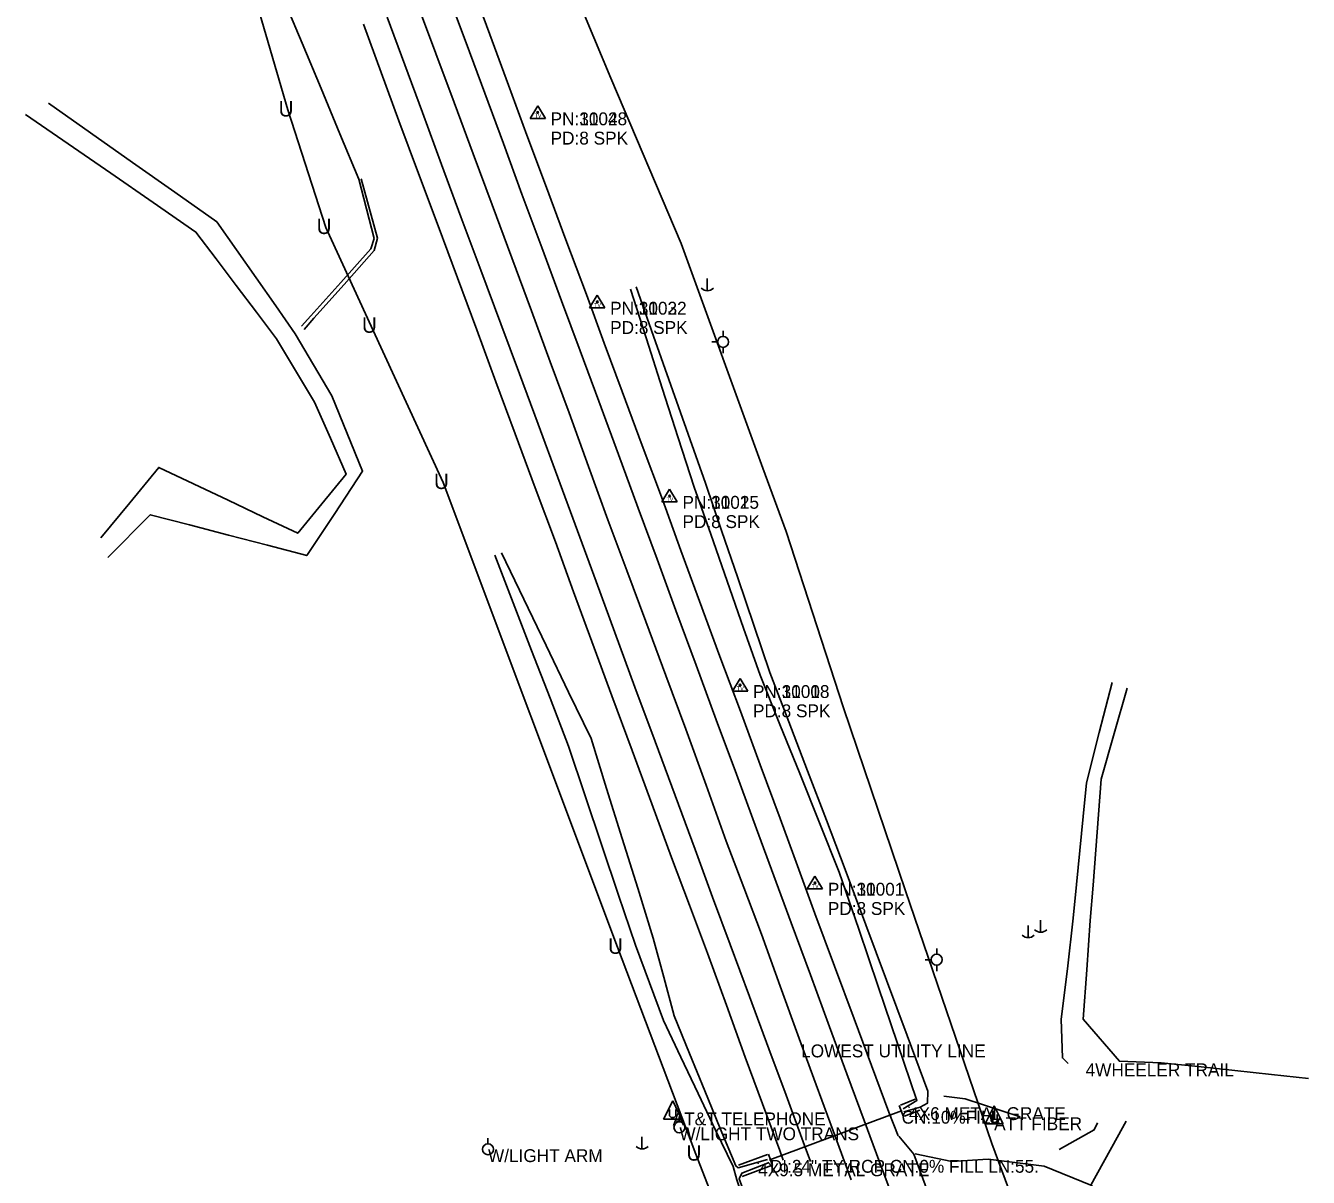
# Model space of a CAD drawing. Extents: x 954793 to 988390, y 1867850 to 1924428.
# Drawn here: x 987603.9 to 988102.4, y 1868765.9 to 1869213.7 of the extents above; entities that cross this region are included whole.
import ezdxf

# ---------------------------------------------------------------- set-up
doc = ezdxf.new("R2010")
doc.units = 0
for name, color, linetype in [('Default', 7, 'Continuous'), ('S_CROSS_DRAIN', 7, 'Continuous'), ('S_CROSS_DRAIN_ANNOT', 7, 'Continuous'), ('S_DITCHLINE', 7, 'Continuous'), ('S_DRG_PT_SYM', 7, 'Continuous'), ('S_DRIVEWAY', 7, 'Continuous'), ('S_EDGE_PAVEMENT', 7, 'Continuous'), ('S_ELECTRIC_UTILITIES_ANNOT', 7, 'Continuous'), ('S_FIBER_OPTIC_CABLE', 7, 'Continuous'), ('S_GRD_PT_SYM', 7, 'Continuous'), ('S_MSC_PT_SYM', 7, 'Continuous'), ('S_PAVEMENT_CROWN', 7, 'Continuous'), ('S_SECONDARY_CTL', 7, 'Continuous'), ('S_SECONDARY_CTL_ANNOT', 7, 'Continuous'), ('S_SHOULDER', 7, 'Continuous'), ('S_SURVEY_TEXT_ANNOT', 7, 'Continuous'), ('S_TRAILS', 7, 'Continuous'), ('S_UNDERGROUND_CABLE', 7, 'Continuous'), ('S_UTILITY_POLE', 7, 'Continuous'), ('S_UTILITY_POLE_ANNOT', 7, 'Continuous'), ('S_UTL_PT_SYM', 7, 'Continuous'), ('S_WALL', 7, 'Continuous')]:
    doc.layers.add(name, color=color, linetype=linetype)

msp = doc.modelspace()

# ---------------------------------------------------------------- linework, layer by layer
at = {"layer": 'S_CROSS_DRAIN'}
msp.add_line((987893.14, 1868772.73), (987944.34, 1868791.8), dxfattribs=at)
at = {"layer": 'S_DITCHLINE'}
for points in [[(987711.07, 1869096.8), (987714.66, 1869100.79), (987726.32, 1869113.83), (987737.97, 1869126.87), (987739.33, 1869130.88), (987733.37, 1869153.95), (987726.02, 1869171.59), (987718.67, 1869189.23), (987711.33, 1869206.87), (987703.98, 1869224.51)], [(987635.85, 1869006.89), (987652.28, 1869023.55), (987667.49, 1869019.58), (987682.7, 1869015.62), (987697.92, 1869011.65), (987713.13, 1869007.68), (987723.98, 1869024.06), (987734.84, 1869040.44), (987728.87, 1869055.08), (987722.89, 1869069.73), (987715.78, 1869081.78), (987708.67, 1869093.82), (987701.05, 1869104.72), (987693.42, 1869115.61), (987685.8, 1869126.5), (987678.17, 1869137.4), (987661.81, 1869148.93), (987645.45, 1869160.45), (987629.09, 1869171.98), (987612.73, 1869183.51)], [(987633.03, 1869014.52), (987644.3, 1869028.21), (987655.58, 1869041.9), (987669.09, 1869035.52), (987682.59, 1869029.13), (987696.1, 1869022.75), (987709.61, 1869016.36), (987719.01, 1869027.81), (987728.42, 1869039.27), (987722.3, 1869053.3), (987716.18, 1869067.33), (987708.78, 1869079.62), (987701.39, 1869091.9), (987693.55, 1869102.28), (987685.71, 1869112.67), (987677.86, 1869123.05), (987670.02, 1869133.44), (987653.48, 1869144.85), (987636.94, 1869156.27), (987620.4, 1869167.68), (987603.86, 1869179.1)], [(987712.1, 1869095.56), (987715.9, 1869099.89), (987727.62, 1869113.08), (987739.35, 1869126.26), (987740.57, 1869131.03), (987734.29, 1869154.07)], [(987944.91, 1868792.52), (987950.32, 1868795.76), (987942.78, 1868817.97), (987935.23, 1868840.18), (987927.68, 1868862.39), (987920.13, 1868884.61), (987912.43, 1868903.74), (987904.72, 1868922.88), (987897.02, 1868942.02), (987889.32, 1868961.16), (987882.93, 1868979.43), (987876.53, 1868997.69), (987870.14, 1869015.95), (987863.75, 1869034.22), (987857.54, 1869053.46), (987851.33, 1869072.71), (987845.12, 1869091.96), (987838.91, 1869111.21)], [(987945.24, 1868791.46), (987951.57, 1868793.19), (987954.39, 1868794.73), (987954.59, 1868799.5), (987946.55, 1868821.03), (987938.51, 1868842.56), (987930.47, 1868864.09), (987922.43, 1868885.61), (987915.11, 1868904.77), (987907.79, 1868923.92), (987900.47, 1868943.07), (987893.15, 1868962.22), (987886.9, 1868980.61), (987880.64, 1868999), (987874.39, 1869017.39), (987868.14, 1869035.78), (987861.39, 1869054.85), (987854.64, 1869073.92), (987847.89, 1869093), (987841.14, 1869112.07)], [(987903.49, 1868695.28), (987897.13, 1868714.75), (987890.76, 1868734.22), (987885.5, 1868749.56), (987880.23, 1868764.91), (987878.83, 1868770.15), (987872.06, 1868784.34), (987865.3, 1868798.52), (987858.54, 1868812.7), (987851.78, 1868826.88), (987846.31, 1868841.55), (987840.85, 1868856.22), (987834.35, 1868875.57), (987827.85, 1868894.92), (987821.35, 1868914.27), (987814.85, 1868933.62), (987807.68, 1868952.16), (987800.51, 1868970.69), (987793.34, 1868989.23), (987786.17, 1869007.76)], [(987892.25, 1868772.86), (987880.75, 1868769.69), (987879.85, 1868770.38), (987873.86, 1868784.96), (987867.87, 1868799.55), (987861.88, 1868814.13), (987855.89, 1868828.71), (987851.86, 1868843.81), (987847.83, 1868858.91), (987841.78, 1868878.31), (987835.74, 1868897.71), (987829.69, 1868917.12), (987823.64, 1868936.52), (987814.92, 1868954.58), (987806.2, 1868972.65), (987797.48, 1868990.71), (987788.76, 1869008.78)], [(987990.37, 1868789.52), (987969.05, 1868796.5), (987960.71, 1868797.45)], [(987905.32, 1868695.02), (987898.91, 1868714.97), (987892.51, 1868734.92), (987886.89, 1868750.13), (987881.26, 1868765.33), (987882.21, 1868767.55), (987892.86, 1868771.75)]]:
    msp.add_lwpolyline(points, dxfattribs=at)
at = {"layer": 'S_DRG_PT_SYM'}
for points in [[(987944.34, 1868791.8), (987944.34, 1868791.85), (987944.34, 1868791.8), (987944.29, 1868791.8), (987944.34, 1868791.8), (987944.34, 1868791.75), (987944.34, 1868791.8), (987944.39, 1868791.8)], [(987893.14, 1868772.73), (987893.14, 1868772.78), (987893.14, 1868772.73), (987893.09, 1868772.73), (987893.14, 1868772.73), (987893.14, 1868772.68), (987893.14, 1868772.73), (987893.19, 1868772.73)]]:
    msp.add_lwpolyline(points, dxfattribs=at)
at = {"layer": 'S_DRIVEWAY'}
for points in [[(987962.03, 1868730.96), (987960.37, 1868744.14), (987954.75, 1868759.55), (987949.14, 1868774.97), (987943.2, 1868781.9)], [(988084.35, 1868715.79), (988062.66, 1868718.35), (988051.03, 1868738.3), (988034.45, 1868750.58), (988017.86, 1868762.86), (987999.71, 1868770.22), (987977.93, 1868773.05), (987963.85, 1868772.04), (987949.58, 1868775.12)]]:
    msp.add_lwpolyline(points, dxfattribs=at)
at = {"layer": 'S_EDGE_PAVEMENT'}
for points in [[(987943.85, 1868750.23), (987936.81, 1868769.13), (987929.77, 1868788.04), (987923.06, 1868806.23), (987916.35, 1868824.43), (987908.88, 1868844.68), (987901.41, 1868864.93), (987894.67, 1868883.2), (987887.94, 1868901.46), (987880.12, 1868922.64), (987872.31, 1868943.83), (987864.46, 1868965.06), (987856.61, 1868986.3), (987849.29, 1869006.21), (987841.96, 1869026.13), (987834.3, 1869046.93), (987826.63, 1869067.74), (987819.39, 1869087.2), (987812.16, 1869106.66), (987804.46, 1869127.42), (987796.75, 1869148.18), (987789.55, 1869167.8), (987782.35, 1869187.43), (987775.07, 1869206.93), (987767.8, 1869226.43)], [(987908.95, 1868772.07), (987906.1, 1868779.8), (987899.43, 1868797.85), (987892.75, 1868815.9), (987885.21, 1868836.18), (987877.67, 1868856.47), (987870.89, 1868874.92), (987864.1, 1868893.37), (987856.31, 1868914.36), (987848.52, 1868935.34), (987840.71, 1868956.52), (987832.9, 1868977.7), (987825.63, 1868997.52), (987818.36, 1869017.33), (987810.71, 1869038.02), (987803.07, 1869058.71), (987795.81, 1869078.24), (987788.55, 1869097.77), (987780.79, 1869118.57), (987773.03, 1869139.36), (987765.56, 1869159.64), (987758.09, 1869179.93), (987751.22, 1869198.45), (987744.34, 1869216.97)]]:
    msp.add_lwpolyline(points, dxfattribs=at)
at = {"layer": 'S_FIBER_OPTIC_CABLE'}
for p, q in [((987831.33, 1869193.21), (987795.61, 1869278.55)), ((987858.7, 1869128.99), (987831.33, 1869193.21)), ((987890.46, 1869041.59), (987858.7, 1869128.99)), ((987899.49, 1869016.95), (987890.46, 1869041.59)), ((987921.71, 1868948.43), (987899.49, 1869016.95)), ((987945.83, 1868877.35), (987921.71, 1868948.43)), ((987979.41, 1868779.14), (987945.83, 1868877.35)), ((988003.79, 1868713.46), (987979.41, 1868779.14))]:
    msp.add_line(p, q, dxfattribs=at)
at = {"layer": 'S_GRD_PT_SYM'}
msp.add_lwpolyline([(987905.29, 1868817.58), (987905.29, 1868817.63), (987905.29, 1868817.58), (987905.24, 1868817.58), (987905.29, 1868817.58), (987905.29, 1868817.53), (987905.29, 1868817.58), (987905.34, 1868817.58)], dxfattribs=at)
at = {"layer": 'S_MSC_PT_SYM'}
for points in [[(987947.25, 1868793.2), (987947.25, 1868793.25), (987947.25, 1868793.2), (987947.2, 1868793.2), (987947.25, 1868793.2), (987947.25, 1868793.15), (987947.25, 1868793.2), (987947.3, 1868793.2)], [(987888.6, 1868771.37), (987888.6, 1868771.42), (987888.6, 1868771.37), (987888.55, 1868771.37), (987888.6, 1868771.37), (987888.6, 1868771.32), (987888.6, 1868771.37), (987888.65, 1868771.37)]]:
    msp.add_lwpolyline(points, dxfattribs=at)
at = {"layer": 'S_PAVEMENT_CROWN'}
msp.add_lwpolyline([(987924.74, 1868765), (987917.72, 1868784.02), (987911.13, 1868801.96), (987904.54, 1868819.91), (987897.19, 1868840.21), (987889.84, 1868860.51), (987882.99, 1868878.55), (987876.15, 1868896.59), (987868.33, 1868918.35), (987860.5, 1868940.11), (987852.71, 1868961.06), (987844.92, 1868982), (987837.53, 1869001.8), (987830.14, 1869021.59), (987822.62, 1869042.33), (987815.1, 1869063.08), (987807.79, 1869082.94), (987800.47, 1869102.81), (987792.81, 1869123.38), (987785.15, 1869143.94), (987777.79, 1869163.85), (987770.43, 1869183.76), (987763.29, 1869202.83), (987756.15, 1869221.91)], dxfattribs=at)
at = {"layer": 'S_SECONDARY_CTL'}
for p, q in [((987802.91, 1869182.55), (987799.9, 1869177.6)), ((987802.91, 1869182.55), (987805.86, 1869177.6)), ((987799.9, 1869177.6), (987805.86, 1869177.6)), ((987826.05, 1869108.92), (987823.04, 1869103.96)), ((987826.05, 1869108.92), (987828.99, 1869103.96)), ((987823.04, 1869103.96), (987828.99, 1869103.96)), ((987854.16, 1869033.46), (987851.15, 1869028.5)), ((987854.16, 1869033.46), (987857.1, 1869028.5)), ((987851.15, 1869028.5), (987857.1, 1869028.5)), ((987881.57, 1868959.9), (987878.56, 1868954.94)), ((987881.57, 1868959.9), (987884.52, 1868954.94)), ((987878.56, 1868954.94), (987884.52, 1868954.94)), ((987910.67, 1868883.05), (987907.66, 1868878.1)), ((987910.67, 1868883.05), (987913.62, 1868878.1)), ((987907.66, 1868878.1), (987913.62, 1868878.1))]:
    msp.add_line(p, q, dxfattribs=at)
for centre, radius in [((987802.91, 1869179.94), 0.311), ((987802.91, 1869179.94), 0.183), ((987802.91, 1869179.94), 0.103), ((987826.05, 1869106.31), 0.311), ((987826.05, 1869106.31), 0.183), ((987826.05, 1869106.31), 0.103), ((987854.16, 1869030.85), 0.311), ((987854.16, 1869030.85), 0.183), ((987854.16, 1869030.85), 0.103), ((987881.57, 1868957.29), 0.311), ((987881.57, 1868957.29), 0.183), ((987881.57, 1868957.29), 0.103), ((987910.67, 1868880.44), 0.311), ((987910.67, 1868880.44), 0.183), ((987910.67, 1868880.44), 0.103)]:
    msp.add_circle(centre, radius, dxfattribs=at)
at = {"layer": 'S_SHOULDER'}
for points in [[(987943.04, 1868782.07), (987939.32, 1868791.21), (987932.63, 1868809.38), (987925.94, 1868827.55), (987918.3, 1868848.04), (987910.67, 1868868.54), (987903.9, 1868887), (987897.12, 1868905.46), (987889.39, 1868926.28), (987881.66, 1868947.1), (987873.73, 1868968.48), (987865.79, 1868989.87), (987858.59, 1869009.66), (987851.39, 1869029.46), (987843.54, 1869050.44), (987835.69, 1869071.42), (987828.76, 1869090.26), (987821.83, 1869109.11), (987813.87, 1869130.43), (987805.91, 1869151.75), (987798.7, 1869171.11), (987791.5, 1869190.47), (987784.24, 1869210.19), (987776.97, 1869229.91)], [(987898.36, 1868772.64), (987896.98, 1868776.33), (987890.29, 1868794.52), (987883.59, 1868812.7), (987876.26, 1868832.88), (987868.92, 1868853.06), (987861.91, 1868871.7), (987854.91, 1868890.34), (987847.29, 1868911.12), (987839.66, 1868931.89), (987831.77, 1868953.08), (987823.87, 1868974.27), (987816.81, 1868993.61), (987809.75, 1869012.94), (987801.91, 1869033.96), (987794.07, 1869054.98), (987786.67, 1869075.21), (987779.28, 1869095.44), (987771.76, 1869115.64), (987764.24, 1869135.83), (987756.6, 1869156.24), (987748.95, 1869176.64), (987742.06, 1869195.42), (987735.17, 1869214.2)]]:
    msp.add_lwpolyline(points, dxfattribs=at)
at = {"layer": 'S_TRAILS'}
for points in [[(988009.07, 1868810.14), (988006.86, 1868812.38), (988006.42, 1868827.41), (988008.76, 1868847.04), (988011.09, 1868866.67), (988012.38, 1868879.84), (988013.66, 1868893.02), (988014.95, 1868906.19), (988016.23, 1868919.36), (988021.18, 1868938.82), (988026.12, 1868958.27)], [(988102.44, 1868804.42), (988088.14, 1868805.94), (988073.85, 1868807.46), (988059.55, 1868808.98), (988045.26, 1868810.5), (988029, 1868811.1), (988014.88, 1868827.45), (988016.29, 1868846.62), (988017.69, 1868865.79), (988018.76, 1868879.52), (988019.82, 1868893.25), (988020.89, 1868906.99), (988021.96, 1868920.72), (988026.97, 1868938.44), (988031.98, 1868956.16)], [(988005.63, 1868776.73), (988019.25, 1868784.35), (988020.54, 1868787.07)], [(988017.86, 1868762.86), (988028.18, 1868781.48), (988031.66, 1868787.72)]]:
    msp.add_lwpolyline(points, dxfattribs=at)
at = {"layer": 'S_UNDERGROUND_CABLE'}
for p, q in [((987705.8, 1869180.89), (987692.34, 1869226.8)), ((987720.59, 1869135.2), (987705.8, 1869180.89)), ((987738.2, 1869096.82), (987720.59, 1869135.2)), ((987766.2, 1869036.07), (987738.2, 1869096.82)), ((987833.85, 1868855.36), (987766.2, 1869036.07)), ((987864.37, 1868774.97), (987833.85, 1868855.36)), ((987855.36, 1868795.69), (987851.83, 1868788.6)), ((987854.16, 1868789.84), (987854.16, 1868792.28)), ((987855.36, 1868795.69), (987858.85, 1868788.6)), ((987856.52, 1868792.28), (987856.52, 1868789.84)), ((987980.31, 1868793.8), (987976.78, 1868786.71)), ((987980.31, 1868793.8), (987983.79, 1868786.71)), ((987851.83, 1868788.6), (987858.85, 1868788.6)), ((987854.78, 1868789.18), (987854.16, 1868789.84)), ((987855.98, 1868789.18), (987854.78, 1868789.18)), ((987856.52, 1868789.84), (987855.98, 1868789.18)), ((987976.78, 1868786.71), (987983.79, 1868786.71)), ((987979.1, 1868787.95), (987979.1, 1868790.39)), ((987979.72, 1868787.29), (987979.1, 1868787.95)), ((987980.93, 1868787.29), (987979.72, 1868787.29)), ((987981.47, 1868787.95), (987980.93, 1868787.29)), ((987981.47, 1868790.39), (987981.47, 1868787.95)), ((987908.46, 1868661.62), (987864.37, 1868774.97))]:
    msp.add_line(p, q, dxfattribs=at)
at = {"layer": 'S_UTILITY_POLE'}
for p, q in [((987868.77, 1869115.34), (987868.77, 1869110.61)), ((987872.86, 1869090.71), (987870.54, 1869090.71)), ((987874.96, 1869092.84), (987874.96, 1869095.08)), ((987875.03, 1869086.29), (987875.03, 1869088.61)), ((987993.5, 1868863.84), (987993.5, 1868859.12)), ((987998.35, 1868865.94), (987998.35, 1868861.21)), ((987957.97, 1868852.68), (987957.97, 1868854.92)), ((987955.88, 1868850.55), (987953.56, 1868850.55)), ((987958.05, 1868846.13), (987958.05, 1868848.45)), ((987857.84, 1868787.5), (987857.84, 1868789.61)), ((987843.43, 1868781.74), (987843.43, 1868777.01)), ((987783.45, 1868779.01), (987783.45, 1868781.12))]:
    msp.add_line(p, q, dxfattribs=at)
for centre in [(987874.96, 1869090.73), (987957.98, 1868850.57), (987857.97, 1868785.36), (987783.57, 1868776.87)]:
    msp.add_circle(centre, 2.13, dxfattribs=at)
for centre in [(987868.84, 1869114.04), (987998.41, 1868864.63), (987993.57, 1868862.54), (987843.49, 1868780.43)]:
    msp.add_arc(centre, 3.41, 226.3972, 313.6028, dxfattribs=at)
at = {"layer": 'S_UTL_PT_SYM'}
for points in [[(987831.33, 1869193.21), (987831.33, 1869193.26), (987831.33, 1869193.21), (987831.28, 1869193.21), (987831.33, 1869193.21), (987831.33, 1869193.16), (987831.33, 1869193.21), (987831.38, 1869193.21)], [(987858.7, 1869128.99), (987858.7, 1869129.04), (987858.7, 1869128.99), (987858.65, 1869128.99), (987858.7, 1869128.99), (987858.7, 1869128.94), (987858.7, 1869128.99), (987858.75, 1869128.99)], [(987890.46, 1869041.59), (987890.46, 1869041.64), (987890.46, 1869041.59), (987890.41, 1869041.59), (987890.46, 1869041.59), (987890.46, 1869041.54), (987890.46, 1869041.59), (987890.51, 1869041.59)], [(987899.49, 1869016.95), (987899.49, 1869017), (987899.49, 1869016.95), (987899.44, 1869016.95), (987899.49, 1869016.95), (987899.49, 1869016.9), (987899.49, 1869016.95), (987899.54, 1869016.95)], [(987921.71, 1868948.43), (987921.71, 1868948.48), (987921.71, 1868948.43), (987921.66, 1868948.43), (987921.71, 1868948.43), (987921.71, 1868948.38), (987921.71, 1868948.43), (987921.76, 1868948.43)], [(987945.83, 1868877.35), (987945.83, 1868877.4), (987945.83, 1868877.35), (987945.78, 1868877.35), (987945.83, 1868877.35), (987945.83, 1868877.3), (987945.83, 1868877.35), (987945.88, 1868877.35)], [(987905.29, 1868817.58), (987905.29, 1868817.63), (987905.29, 1868817.58), (987905.24, 1868817.58), (987905.29, 1868817.58), (987905.29, 1868817.53), (987905.29, 1868817.58), (987905.34, 1868817.58)], [(987979.41, 1868779.14), (987979.41, 1868779.19), (987979.41, 1868779.14), (987979.36, 1868779.14), (987979.41, 1868779.14), (987979.41, 1868779.09), (987979.41, 1868779.14), (987979.46, 1868779.14)]]:
    msp.add_lwpolyline(points, dxfattribs=at)
at = {"layer": 'S_WALL'}
for points in [[(987945.08, 1868789.47), (987943.34, 1868793.93)], [(987943.88, 1868793.95), (987949.67, 1868796.32)], [(987951.48, 1868792.02), (987945.52, 1868789.77)], [(987892.23, 1868774.8), (987880.9, 1868770.62)], [(987894.22, 1868770.53), (987892.61, 1868774.98)], [(987882.41, 1868766.3), (987893.74, 1868770.48)]]:
    msp.add_lwpolyline(points, dxfattribs=at)

# ---------------------------------------------------------------- texts
at = {"layer": 'Default'}
for p in [(987702.17, 1869178.34), (987716.96, 1869132.66), (987734.57, 1869094.27), (987762.57, 1869033.52), (987830.22, 1868852.82), (987860.74, 1868772.43)]:
    msp.add_text('U', height=6, rotation=360, dxfattribs=at).set_placement(p)
at = {"layer": 'S_CROSS_DRAIN_ANNOT'}
for s, p in [('CN:10%FILL', (987944.34, 1868786.8)), ('DI:24" TY:RCP CN:0% FILL LN:55.', (987893.14, 1868767.73))]:
    msp.add_text(s, height=5, dxfattribs=at).set_placement(p)
at = {"layer": 'S_ELECTRIC_UTILITIES_ANNOT'}
msp.add_text('LOWEST UTILITY LINE', height=5, dxfattribs=at).set_placement((987905.29, 1868812.58))
at = {"layer": 'S_SECONDARY_CTL'}
for p in [(987801.71, 1869177.93), (987824.84, 1869104.3), (987852.95, 1869028.84), (987880.37, 1868955.27), (987909.47, 1868878.43)]:
    msp.add_text('TV', height=1.5, rotation=360, dxfattribs=at).set_placement(p)
at = {"layer": 'S_SECONDARY_CTL_ANNOT'}
for s, p in [('PN:1104', (987807.91, 1869174.94)), ('PN:30028', (987807.91, 1869174.94)), ('PD:8 SPK', (987807.91, 1869167.44)), ('PD:8 SPK', (987807.91, 1869167.44)), ('PN:1103', (987831.05, 1869101.31)), ('PN:30022', (987831.05, 1869101.31)), ('PD:8 SPK', (987831.05, 1869093.81)), ('PD:8 SPK', (987831.05, 1869093.81)), ('PN:1102', (987859.16, 1869025.85)), ('PN:30015', (987859.16, 1869025.85)), ('PD:8 SPK', (987859.16, 1869018.35)), ('PD:8 SPK', (987859.16, 1869018.35)), ('PN:1101', (987886.57, 1868952.29)), ('PN:30008', (987886.57, 1868952.29)), ('PD:8 SPK', (987886.57, 1868944.79)), ('PD:8 SPK', (987886.57, 1868944.79)), ('PN:1100', (987915.67, 1868875.44)), ('PN:30001', (987915.67, 1868875.44)), ('PD:8 SPK', (987915.67, 1868867.94)), ('PD:8 SPK', (987915.67, 1868867.94))]:
    msp.add_text(s, height=5, dxfattribs=at).set_placement(p)
at = {"layer": 'S_SURVEY_TEXT_ANNOT'}
for s, p in [('4WHEELER TRAIL', (988015.87, 1868805.23)), ('4X6 METAL GRATE', (987947.25, 1868788.2)), ('4X9.5 METAL GRATE', (987888.6, 1868766.37))]:
    msp.add_text(s, height=5, dxfattribs=at).set_placement(p)
at = {"layer": 'S_UTILITY_POLE_ANNOT'}
for s, p in [('AT&T TELEPHONE', (987855.36, 1868786.16)), ('ATT FIBER', (987980.31, 1868784.27)), ('W/LIGHT TWO TRANS', (987857.97, 1868780.36)), ('W/LIGHT ARM', (987783.57, 1868771.87))]:
    msp.add_text(s, height=5, dxfattribs=at).set_placement(p)

doc.saveas('drawing.dxf')
